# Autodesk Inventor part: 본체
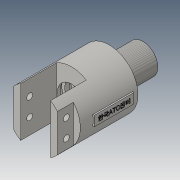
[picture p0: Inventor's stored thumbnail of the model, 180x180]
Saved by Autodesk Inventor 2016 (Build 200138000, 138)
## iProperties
Created: 2019-02
Part Number: 본체
Material: 일반
Document SubType Name: Modeling
Designer: Administrator
Density: 1 g/cm^3
Appearance: 기본값
Author: Administrator
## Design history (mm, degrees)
sketch "스케치1"
  geometry: C1 r 29 at (0, 0); 1 further point
  constraints: 1 centre point, 1 coincident
  dimensions: "d0" = 58 diameter of C1
extrude "돌출1" new body sketch "스케치1" distance "d1" = 74; taper "d2" = 0 deg
sketch "스케치2"
  geometry: C1 r 13 at (0, 0); 1 further point
  constraints: 1 centre point, 1 coincident
  dimensions: "d3" = 26 diameter of C1
extrude "돌출2" join sketch "스케치2" distance "d4" = 5; taper "d5" = 0 deg
sketch "스케치3"
  geometry: C1 r 15 at (0, 0); 1 further point
  constraints: 1 centre point, 1 coincident
  dimensions: "d6" = 30 diameter of C1
extrude "돌출3" join sketch "스케치3" distance "d7" = 29; taper "d8" = 0 deg
feature "스레드1" dims "d9" = 10, "d10" = 0
node "작업 평면1"
sketch "스케치4"
  geometry: L1 (15, -36)-(-15, -36); L2 (-15, -36)-(-15, 0); L3 (-15, 0)-(15, 0); L4 (15, 0)-(15, -36); 2 further points
  constraints: 8 end point, 2 coincident, 2 parallel, 1 horizontal, 1 midpoint, 1 perpendicular
  dimensions: "d12" = 30 distance of L2.end L3.end; "d13" = 36 distance of L1.end L2.end
extrude "돌출4" cut sketch "스케치4" stored distance "d14" = 59; taper "d15" = 0 deg
sketch "스케치5"
  geometry: L1 (29, -16)-(22, -16); L2 (22, -16)-(22, 0); L3 (22, 0)-(29, 0); L4 (29, 0)-(29, -16); L5 (-22, -16)-(-29, -16); L6 (-29, -16)-(-29, 0); L7 (-29, 0)-(-22, 0); L8 (-22, 0)-(-22, -16); L9 (15, -36)-(15, 0) reference; L10 (15, 0)-(15, 0) reference; L11 (15, 0)-(15, -36) reference; L12 (15, -36)-(-15, -36) reference; L13 (-15, -36)-(-15, 0) reference; L14 (-15, 0)-(-15, 0) reference; L15 (-15, 0)-(-15, -36) reference; L16 (-15, -36)-(15, -36) reference; L17 (-29, -74)-(29, -74) reference; L18 (15, 0)-(29, 0) reference; L19 (29, 0)-(29, -74) reference; L20 (-29, 0)-(-15, 0) reference; L21 (-29, 0)-(-29, -74) reference; 1 further point
  constraints: 16 end point, 5 parallel, 4 coincident, 2 horizontal, 2 perpendicular
  dimensions: "d16" = 7 distance of L2.end L3.end; "d17" = 16 distance of L3.end L1.start; "d18" = 7 distance of L6.end L7.end
extrude "돌출5" cut sketch "스케치5" stored distance "d19" = 0; taper "d20" = 0 deg
sketch "스케치6"
  geometry: L1 (16, 0)-(16, 37.789) reference; L2 (0, 37.789)-(16, 37.789) reference; L3 (0, 0)-(0, 37.789) reference; L4 (16, 0)-(0, 0) reference; L5 (74, 0)-(16, 0) reference; L6 (74, 37.789)-(74, 0) reference; L7 (16, 37.789)-(74, 37.789) reference; C1 r 3 at (9, 27.894); C2 r 3 at (9, 9.894); 1 further point
  constraints: 2 centre point, 1 vertical alignment
  dimensions: "d21" = 6 diameter of C1; "d22" = 6 diameter of C2; "d23" = 18 distance of C2.centre C1.centre; "d24" = 9 horizontal distance of C2.centre point (0, 18.894); "d25" = 9 horizontal distance of C1.centre point (0, 18.894)
extrude "돌출6" cut sketch "스케치6" stored distance "d27" = 59; taper "d28" = 0 deg
sketch "스케치8"
  geometry: C1 r 14 at (0, 0); 1 further point
  constraints: 1 centre point, 1 coincident
  dimensions: "d37" = 28 diameter of C1
extrude "돌출7" cut sketch "스케치8" distance "d38" = 2.65; taper "d39" = 0 deg
sketch "스케치10"
  geometry: C1 r 17 at (0, 0); 1 further point
  constraints: 1 centre point, 1 coincident
  dimensions: "d41" = 34 diameter of C1
extrude "돌출8" cut sketch "스케치10" distance "d42" = 4.7; taper "d43" = 0 deg
sketch "스케치11"
  geometry: C1 r 14 at (0, 0); 1 further point
  constraints: 1 centre point, 1 coincident
  dimensions: "d44" = 28 diameter of C1
extrude "돌출9" cut sketch "스케치11" distance "d45" = 4.3; taper "d46" = 0 deg
sketch "스케치12"
  geometry: C1 r 17 at (0, 0); 1 further point
  constraints: 1 centre point, 1 coincident
  dimensions: "d47" = 34 diameter of C1
extrude "돌출10" cut sketch "스케치12" distance "d48" = 4.7; taper "d49" = 0 deg
sketch "스케치15"
  geometry: C1 r 14 at (0, 0); 1 further point
  constraints: 1 centre point, 1 coincident
  dimensions: "d56" = 28 diameter of C1
extrude "돌출13" cut sketch "스케치15" distance "d57" = 3.65; taper "d58" = 0 deg
sketch "스케치16"
  geometry: C1 r 16 at (0, 0); 1 further point
  constraints: 1 centre point, 1 coincident
  dimensions: "d59" = 32 diameter of C1
extrude "돌출14" cut sketch "스케치16" distance "d60" = 7; taper "d61" = 0 deg
hole "구멍1" diameter "d64" = 8; stored, may be unused: countersink angle "d68" = 90 deg, drill point angle "d70" = 118 deg; dims "d62" = 10, "d63" = 10, "d65" = 6, "d66" = 4, "d67" = 2, "d69" = 8
hole "구멍2" diameter "d73" = 12.376; stored, may be unused: countersink angle "d77" = 90 deg, drill point angle "d79" = 118 deg; dims "d71" = 10, "d72" = 10, "d74" = 18, "d75" = 4, "d76" = 2, "d78" = 22
node "작업 평면3"
sketch "스케치17"
  geometry: L1 (5, -29)-(-5, -29); L2 (-5, -29)-(-5, -69); L3 (-5, -69)-(5, -69); L4 (5, -69)-(5, -29); L5 (-29, -74)-(29, -74) reference; 2 further points
  constraints: 8 end point, 2 parallel, 1 horizontal, 1 midpoint, 1 perpendicular, 1 vertical alignment
  dimensions: "d82" = 40 distance of L3.end L1.start; "d83" = 10 distance of L1.start L1.end; "d84" = 5 distance between parallel lines of L5 L3
extrude "돌출15" join sketch "스케치17" stored distance "d85" = 7; taper "d86" = 0 deg
sketch "스케치18"
  geometry: L1 (29, 5)-(69, 5) reference; L2 (29, 5)-(29, -5) reference; 4 further points
  constraints: 2 midpoint, 1 horizontal alignment, 1 vertical alignment, 1 other
feature "엠보싱1" sketch "스케치18" dims "d1" = 74, "d2" = 0, "d12" = 30, "d87" = 0.5, "d88" = 0
node "솔리드1"
node "투영된 루프1"
node "절단 모서리 투영1"
other parameters: "d11" = 29
